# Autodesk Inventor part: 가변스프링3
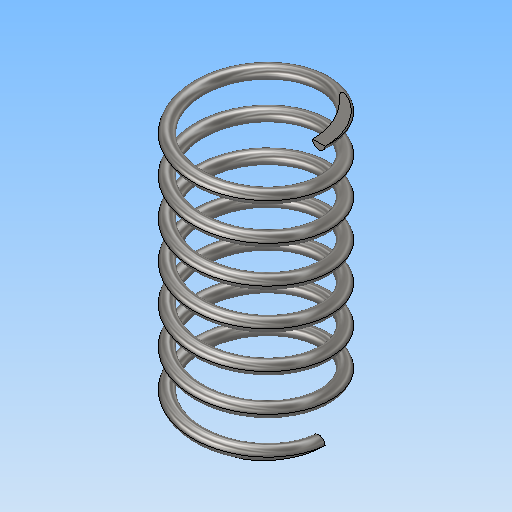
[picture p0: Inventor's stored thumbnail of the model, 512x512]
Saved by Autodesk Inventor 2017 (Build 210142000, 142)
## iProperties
Part Number: 가변스프링3
Material: 스테인레스 스틸
Document SubType Name: Modeling
Designer: MRC
Density: 8 g/cm^3
Appearance: 반연마
Mass: 10.94 g
Surface Area: 27.6363 cm^2
Volume: 1.36751 cm^3
Author: MRC
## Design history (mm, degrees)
sketch "스케치1"
  geometry: L1 (0, 0)-(10, 0); L2 (10, 0)-(10, 41.261); L3 (10, 41.261)-(0, 41.261); L4 (0, 41.261)-(0, 0); C1 r 1 at (10, 0)
  constraints: 8 end point, 2 parallel, 1 centre point, 1 coincident, 1 horizontal, 1 perpendicular
  dimensions: "d0" = 41.2612 distance between parallel lines of L1 L3 (derived); "d1" = 20 diameter of L2 L4; "d2" = 2 diameter of C1
feature "코일1" sketch "스케치1" pitch "d3" = 10; turns "d5" = 7; dims "d4" = 41.2612 (= d0), "d6" = 0, angle "d7" = 90 deg, angle "d8" = 90 deg, "d9" = 0, "d10" = 0
sketch "스케치2"
  geometry: L1 (0, -17.9)-(41.261, -17.9); L2 (41.261, -17.9)-(41.261, 17.9); L3 (41.261, 17.9)-(0, 17.9); L4 (0, 17.9)-(0, -17.9); 4 further points
  constraints: 8 end point, 2 coincident, 2 midpoint, 2 parallel, 1 horizontal, 1 perpendicular
  dimensions: "d11" = 35.80033 distance between parallel lines of L1 L3
extrude "돌출1" sketch "스케치2" stored distance "d12" = 50; taper "d13" = 0 deg
node "솔리드1"
